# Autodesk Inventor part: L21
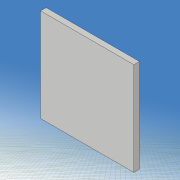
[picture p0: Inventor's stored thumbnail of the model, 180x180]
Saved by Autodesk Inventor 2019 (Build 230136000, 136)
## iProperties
Created: 2021-05
Part Number: L21
Material: 一般
Document SubType Name: Modeling
Designer: kikut
Density: 1 g/cm^3
Appearance: 既定
Mass: 0.00934248 g
Surface Area: 0.426451 cm^2
Volume: 0.00934248 cm^3
Author: kikut
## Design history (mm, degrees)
sketch "スケッチ1"
  geometry: L1 (80, 60)-(-80, 60); L2 (-80, 60)-(-80, -60); L3 (-80, -60)-(80, -60); L4 (80, -60)-(80, 60); L5 (80, 60)-(-80, -60); L6 (-80, 60)-(80, -60); 1 further point
  constraints: 12 end point, 2 midpoint, 2 parallel, 1 horizontal, 1 perpendicular
  dimensions: "d0" = 160 distance of L2.end L3.end; "d1" = 120 distance of L1.end L2.end
extrude "押し出し1" new body sketch "スケッチ1" stored distance "d2" = 0.6; taper "d3" = 0 deg
sketch "スケッチ2"
  geometry: L1 (-140, 0)-(140, 0) reference; L2 (0, -54)-(20, -30); L3 (0, 54)-(20, 30); L4 (0, -3)-(6.514, -3); L5 (6.514, -3)-(16, -6); L6 (16, -6)-(24, -3); L7 (24, -3)-(33.716, -3); L8 (0, 3)-(6.514, 3); L9 (6.514, 3)-(16, 6); L10 (16, 6)-(24, 3); L11 (24, 3)-(33.716, 3); L12 (0, -98)-(0, 98) reference; L13 (-100, -70)-(100, -70); L14 (100, -70)-(100, 70); L15 (100, 70)-(-100, 70); L16 (-100, 70)-(-100, -70); L17 (-100, -70)-(100, 70); L18 (100, -70)-(-100, 70); A1 r 60 centre (54.312, 28.5) between (0, 54) and (0, 3); A2 r 60 centre (54.312, -28.5) between (0, -3) and (0, -54); A3 r 18.111 centre (18, -12) between (20, -30) and (33.716, -3); A4 r 18.111 centre (18, 12) between (33.716, 3) and (20, 30); 1 further point
  constraints: 32 end point, 8 point on circle, 8 symmetric about line, 4 centre point, 3 horizontal, 2 collinear, 2 midpoint, 2 parallel, 1 perpendicular
  dimensions: "d5" = 60 radius of A1; "d6" = 6 distance of L8.start L4.start; "d7" = 108 distance of L3.start L2.start; "d8" = 0 horizontal distance of L3.start L8.start; "d9" = 60 distance of L3.end L2.end; "d10" = 0 horizontal distance of point (0, 0) L3.start; "d11" = 20 horizontal distance of L3.start L3.end; "d12" = 24 distance of A4.centre A3.centre; "d13" = 6 distance of L11.end L7.end; "d14" = 12 distance of L9.end L5.end; "d15" = 16 distance from line of L12 L5.end; "d16" = 24 distance from line of L6.end L12; "d17" = 200 distance of L14.end L15.end; "d18" = 140 distance of L15.end L13.start; "d30" = 18 distance from line of L12 A4.centre
extrude "押し出し2" cut sketch "スケッチ2" stored distance "d19" = 10; taper "d20" = 0 deg
sketch "スケッチ3"
  geometry: L1 (49.705, -17.97)-(33.948, -15.191); L2 (33.948, -15.191)-(34.295, -13.222); L3 (34.295, -13.222)-(50.052, -16); L4 (50.052, -16)-(49.705, -17.97); L5 (49.705, -17.97)-(34.295, -13.222); L6 (33.948, -15.191)-(50.052, -16); L7 (50.052, 16)-(34.295, 13.222); L8 (34.295, 13.222)-(33.948, 15.191); L9 (33.948, 15.191)-(49.705, 17.97); L10 (49.705, 17.97)-(50.052, 16); L11 (50.052, 16)-(33.948, 15.191); L12 (34.295, 13.222)-(49.705, 17.97); L13 (-112, 0)-(112, 0) reference; L14 (0, -84)-(0, 84) reference; 3 further points
  constraints: 24 end point, 4 midpoint, 4 parallel, 2 perpendicular, 2 symmetric about line
  dimensions: "d21" = 2 distance of L3.end L1.start; "d22" = 2 distance of L9.end L7.start; "d23" = 16 distance of L8.end L9.end; "d24" = 42 distance from line of L14 point (42, 15.596); "d26" = 10 deg angle of L7 L13; "d62" = 16 distance from line of L3.end L13
extrude "押し出し3" join sketch "スケッチ3" distance "d27" = 0.6; taper "d28" = 0 deg
fillet "フィレット1" dims "d31" = 2
fillet "フィレット2" dims "d32" = 1
sketch "スケッチ7"
  geometry: L1 (-20, 60)-(80, 60); L2 (80, 60)-(80, -60); L3 (80, -60)-(-20, -60); L4 (-20, -60)-(-20, 60); L5 (0, -82.207)-(0, 85.793) reference; L6 (-40, 0)-(100, 0) reference; L7 (10, -10)-(20, -10); L8 (20, -10)-(20, -20); L9 (20, -20)-(10, -20); L10 (10, -20)-(10, -10); 1 further point
  constraints: 16 end point, 4 parallel, 2 horizontal, 2 perpendicular, 1 other
  dimensions: "d80" = 120 distance of L3.end L1.start; "d81" = 20 distance between parallel lines of L5 L4; "d82" = 100 distance of L1.start L1.end; "d84" = 10 distance of L8.end L9.end; "d85" = 10 distance of L7.end L8.end; "d86" = 30 distance between parallel lines of L4 L10; "d91" = 40 distance between parallel lines of L3 L9
extrude "押し出し5" cut sketch "スケッチ7" stored distance "d87" = 10; taper "d88" = 0 deg
node "ソリッド1"
